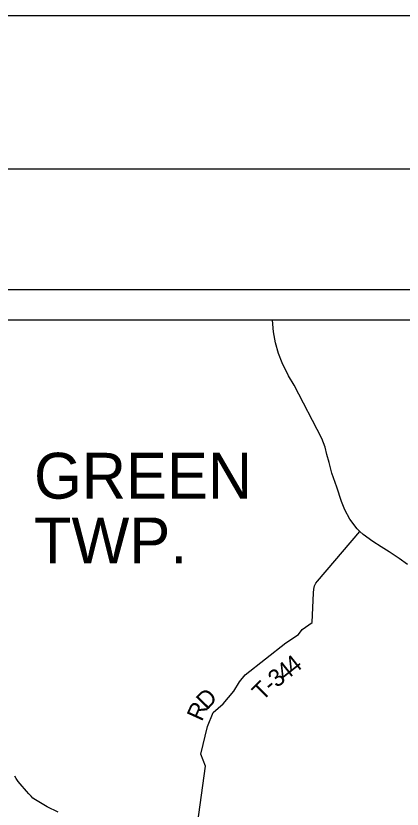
# Model space of a CAD drawing. Extents: x 0 to 34, y 0 to 22.
# Drawn here: x 3.722 to 4.986, y 19.405 to 22 of the extents above; entities that cross this region are included whole.
import ezdxf

# ---------------------------------------------------------------- set-up
doc = ezdxf.new("R2010")
doc.units = 0
for name, color, linetype in [('GM_X_County_Road', 7, 'Continuous'), ('GM_X_State_Route', 7, 'Continuous'), ('GM_X_Township_Road', 7, 'Continuous'), ('GM_X_Township_Road_Text', 7, 'Continuous'), ('GM_X_Township_Text', 7, 'Continuous'), ('SH_Border', 7, 'Continuous'), ('SH_Cut_Line', 7, 'Continuous'), ('SH_Data', 7, 'Continuous')]:
    doc.layers.add(name, color=color, linetype=linetype)

msp = doc.modelspace()

# ---------------------------------------------------------------- linework, layer by layer
at = {"layer": 'GM_X_County_Road'}
msp.add_lwpolyline([(3.8604, 19.3958), (3.8247, 19.4132), (3.7861, 19.4354), (3.7777, 19.4415), (3.7723, 19.4472), (3.7647, 19.455), (3.7572, 19.4641), (3.7507, 19.4718), (3.7429, 19.4807), (3.7303, 19.4959), (3.7237, 19.505), (3.719, 19.5135)], dxfattribs=at)
at = {"layer": 'GM_X_State_Route'}
msp.add_lwpolyline([(5.0031, 20.2056), (4.9759, 20.2251), (4.9434, 20.2468), (4.9169, 20.2632), (4.8896, 20.2807), (4.8578, 20.3032), (4.8474, 20.3135), (4.8385, 20.3223), (4.8147, 20.3538), (4.7981, 20.3842), (4.7876, 20.4112), (4.7718, 20.4587), (4.756, 20.5047), (4.7466, 20.5392), (4.7397, 20.5657), (4.7336, 20.5889), (4.723, 20.6174), (4.6324, 20.7923), (4.6146, 20.8227), (4.5936, 20.8651), (4.5813, 20.8952), (4.5713, 20.93), (4.5652, 20.9665), (4.562, 21.0043), (4.5619, 21.0054)], dxfattribs=at)
at = {"layer": 'GM_X_Township_Road'}
msp.add_lwpolyline([(4.2182, 19.1295), (4.2483, 19.1765), (4.271, 19.227), (4.29, 19.2536), (4.3063, 19.2821), (4.312, 19.3246), (4.3426, 19.5455), (4.3271, 19.5849), (4.3494, 19.6757), (4.3672, 19.7209), (4.4002, 19.7494), (4.4349, 19.791), (4.4544, 19.8214), (4.4723, 19.8447), (4.6051, 19.9498), (4.6473, 19.9767), (4.6591, 19.9924), (4.6913, 20.0153), (4.6955, 20.1127), (4.6966, 20.1246), (4.6995, 20.1357), (4.703, 20.1441), (4.7086, 20.1513), (4.8474, 20.3135)], dxfattribs=at)
at = {"layer": 'SH_Border'}
msp.add_lwpolyline([(1.5, 21.5), (33.5, 21.5), (33.5, 0.5), (1.5, 0.5)], close=True, dxfattribs=at)
at = {"layer": 'SH_Cut_Line'}
msp.add_lwpolyline([(0, 0), (34, 0), (34, 22), (0, 22)], close=True, dxfattribs=at)
at = {"layer": 'SH_Data'}
for p, q in [((1.8763, 21.1054), (8.8763, 21.1054)), ((1.9763, 21.0054), (8.7763, 21.0054))]:
    msp.add_line(p, q, dxfattribs=at)

# ---------------------------------------------------------------- texts
at = {"layer": 'GM_X_Township_Road_Text'}
for s, rotation, p in [('4', 38.2981, (4.6304, 19.8439)), ('4', 38.3916, (4.603, 19.8222)), ('3', 38.8207, (4.5758, 19.8003)), ('T', 44.9333, (4.529, 19.7564)), ('-', 39.9655, (4.5581, 19.7855)), ('D', 45.9196, (4.3472, 19.7278)), ('R', 65.6436, (4.3308, 19.6895))]:
    msp.add_text(s, height=0.0568, rotation=rotation, dxfattribs=at).set_placement(p)
at = {"layer": 'GM_X_Township_Text'}
for s, p in [('GREEN', (3.7819, 20.4208)), ('TWP.', (3.7819, 20.2092))]:
    msp.add_text(s, height=0.15, rotation=0, dxfattribs=at).set_placement(p)

doc.saveas('drawing.dxf')
